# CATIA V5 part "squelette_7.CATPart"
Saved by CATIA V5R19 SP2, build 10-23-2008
Part number: squelette_7
Publications: "Point.1", "Droite.1", "Plan.3"
Bounding box of the stored display mesh (mm): x -10 to 10, y -96 to 0, z 0 to 10
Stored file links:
  M:\EU_thinkMotion\IAO_2010\iao\IAO_MMS_Groupe2\IAO_MMS_Groupe2\sdubois\sdubois\sdubois\IAO_mecanisme\squelette_7.CATPart
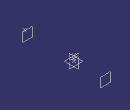
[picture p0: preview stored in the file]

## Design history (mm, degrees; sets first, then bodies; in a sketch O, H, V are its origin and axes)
Set1
  Point1: (0, 0, 5)
  Line1: type PtDir, RefPoint Point1, Direction yz-plane, Start -10, End 10
  Plane1: type Offset, RefPlane zx-plane, Offset 62
  Point2: (0, 0, 0)
  Point3: (0, 0, 10)
  Plane2: type Offset, RefPlane zx-plane, Offset -90
  Point4: (0, -96, 5)
Body1 (main body)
